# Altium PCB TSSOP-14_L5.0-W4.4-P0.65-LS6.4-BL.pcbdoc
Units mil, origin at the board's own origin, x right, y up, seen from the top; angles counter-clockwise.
Board outline 697.43 x 793.77 mil, 2 copper layers (Top Layer, Bottom Layer), stack 0 mil thick; 1 components, 0 nets, 14 pads, 0 vias.
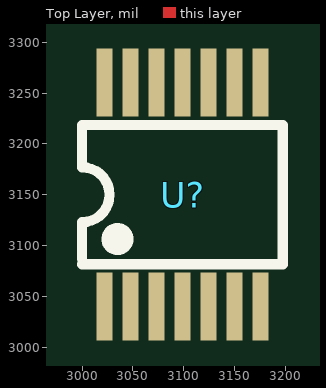
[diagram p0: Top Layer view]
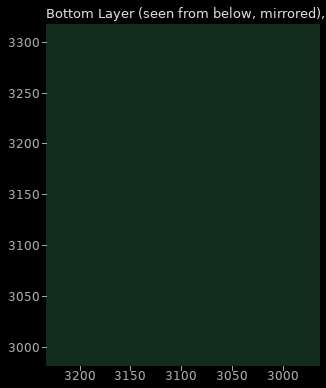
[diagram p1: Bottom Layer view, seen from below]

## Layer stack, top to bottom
Top Layer: signal copper (thickness not stored)
Bottom Layer: signal copper (thickness not stored)

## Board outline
3447.43,2750 2750,2750 2750,3543.77 3447.43,3543.77

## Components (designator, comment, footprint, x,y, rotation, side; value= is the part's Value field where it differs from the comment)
U? "" TSSOP-14_L5.0-W4.4-P0.65-LS6.4-BL 3099,3150.07 r0 top

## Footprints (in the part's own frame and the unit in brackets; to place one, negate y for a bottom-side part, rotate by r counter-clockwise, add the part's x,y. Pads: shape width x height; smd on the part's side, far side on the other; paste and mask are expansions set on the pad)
TSSOP-14_L5.0-W4.4-P0.65-LS6.4-BL [mm]
  rect 0.4x1.7 smd: 1(-1.95,-2.8) 2(-1.3,-2.8) 3(-0.65,-2.8) 4(0,-2.8) 5(0.65,-2.8) 6(1.3,-2.8) 7(1.95,-2.8) 8(1.95,2.8) 9(1.3,2.8) 10(0.65,2.8) 11(0,2.8) 12(-0.65,2.8) 13(-1.3,2.8) 14(-1.95,2.8)
  silkscreen extent -2.51,-1.74 2.5,1.74

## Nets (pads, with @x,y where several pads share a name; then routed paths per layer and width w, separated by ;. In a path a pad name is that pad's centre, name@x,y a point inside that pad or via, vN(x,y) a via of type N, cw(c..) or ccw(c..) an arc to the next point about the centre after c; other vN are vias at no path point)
pads on no net: U?.1 U?.2 U?.3 U?.4 U?.5 U?.6 U?.7 U?.8 U?.9 U?.10 U?.11 U?.12 U?.13 U?.14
